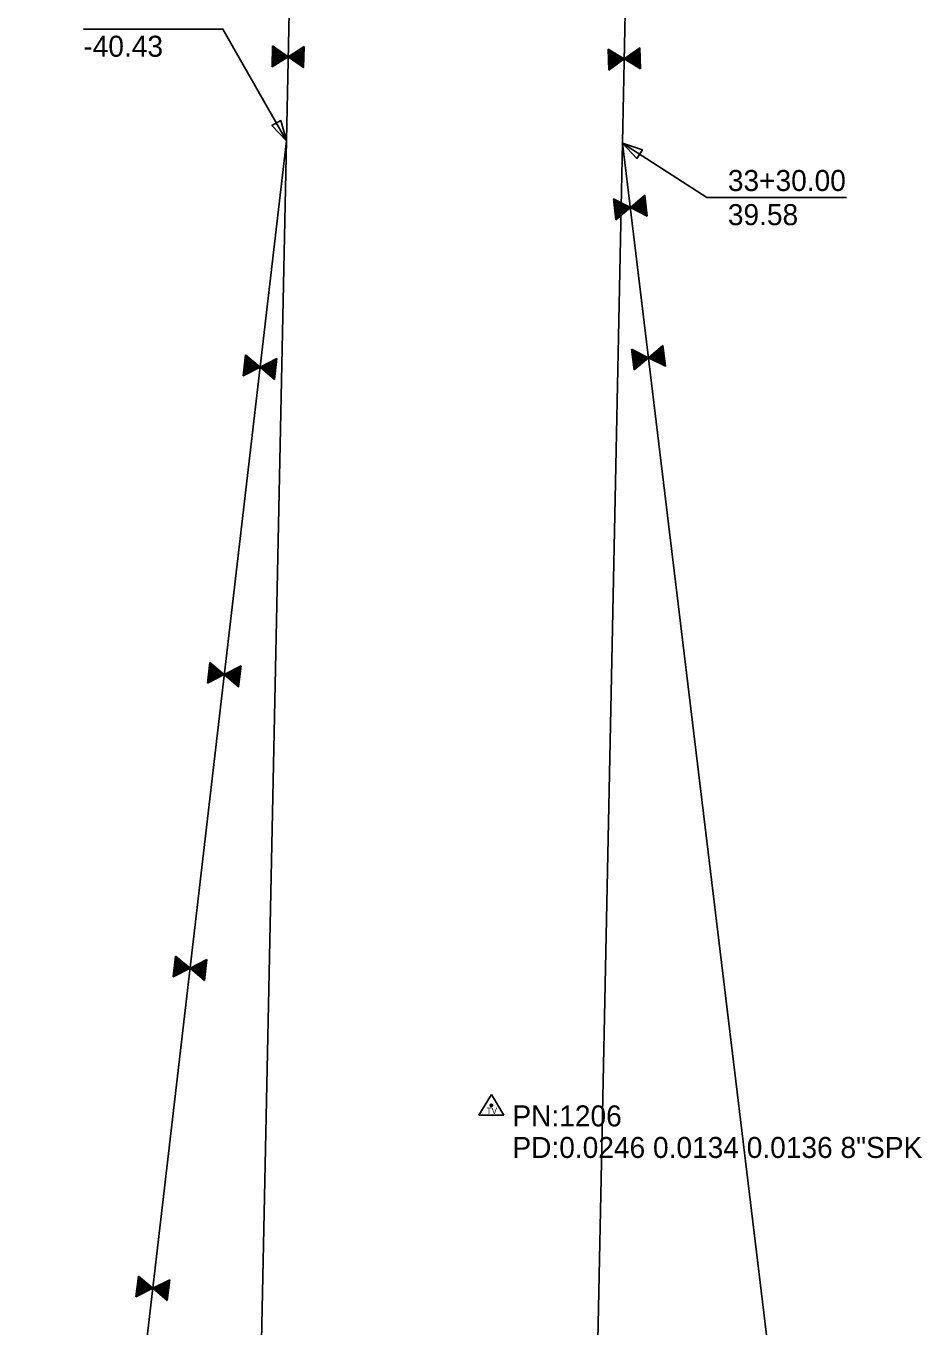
# Model space of a CAD drawing. Extents: x 1443798 to 1476449, y 2041559 to 2057889.
# Drawn here: x 1476148 to 1476361.3, y 2055786.4 to 2056095.8 of the extents above; entities that cross this region are included whole.
import ezdxf

# ---------------------------------------------------------------- set-up
doc = ezdxf.new("R2010")
doc.units = 0
for name, color, linetype in [('Plan Notes', 7, 'Continuous'), ('R_Proposed Fence', 7, 'Continuous'), ('R_ROW', 7, 'Continuous'), ('S_EXIST_ROW', 7, 'Continuous'), ('S_SECONDARY_CTL', 7, 'Continuous'), ('S_SECONDARY_CTL_ANNOT', 7, 'Continuous')]:
    doc.layers.add(name, color=color, linetype=linetype)

msp = doc.modelspace()

# ---------------------------------------------------------------- linework, layer by layer
at = {"layer": 'Plan Notes'}
for p, q in [((1476161.69, 2056095.07), (1476189.92, 2056095.07)), ((1476315.06, 2056055.02), (1476343.29, 2056055.02))]:
    msp.add_line(p, q, dxfattribs=at)
for points in [[(1476210, 2056068.52), (1476194.92, 2056095.07), (1476189.92, 2056095.07)], [(1476290.01, 2056067.99), (1476310.06, 2056055.02), (1476315.06, 2056055.02)]]:
    msp.add_lwpolyline(points, dxfattribs=at)
for points in [[(1476210, 2056068.52), (1476206.55, 2056072.14), (1476208.66, 2056073.34)], [(1476290.01, 2056067.99), (1476294.74, 2056066.37), (1476293.42, 2056064.34)]]:
    msp.add_lwpolyline(points, close=True, dxfattribs=at)
at = {"layer": 'R_Proposed Fence'}
for p, q in [((1476210.06, 2056088.37), (1476206.71, 2056090.7)), ((1476210.42, 2056088.52), (1476206.72, 2056091.1)), ((1476210.32, 2056088.48), (1476206.72, 2056091)), ((1476210.42, 2056088.52), (1476214.22, 2056090.94)), ((1476210.51, 2056088.48), (1476214.22, 2056090.84)), ((1476206.62, 2056086.1), (1476210.42, 2056088.52)), ((1476208.04, 2056087.03), (1476206.65, 2056087.99)), ((1476207.83, 2056086.87), (1476206.65, 2056087.69)), ((1476208.69, 2056087.49), (1476206.67, 2056088.9)), ((1476208.47, 2056087.34), (1476206.67, 2056088.6)), ((1476208.95, 2056087.61), (1476206.68, 2056089.2)), ((1476209.41, 2056087.9), (1476206.69, 2056089.8)), ((1476209.14, 2056087.79), (1476206.69, 2056089.5)), ((1476209.87, 2056088.19), (1476206.7, 2056090.4)), ((1476209.62, 2056088.06), (1476206.7, 2056090.1)), ((1476208.2, 2056087.22), (1476206.8, 2056088.2)), ((1476214.11, 2056085.94), (1476210.42, 2056088.52)), ((1476210.77, 2056088.35), (1476214.21, 2056090.54)), ((1476210.95, 2056088.17), (1476214.2, 2056090.24)), ((1476211.19, 2056088.03), (1476214.2, 2056089.94)), ((1476211.4, 2056087.86), (1476214.19, 2056089.64)), ((1476211.66, 2056087.73), (1476214.18, 2056089.34)), ((1476211.84, 2056087.55), (1476214.18, 2056089.04)), ((1476212.1, 2056087.42), (1476214.17, 2056088.74)), ((1476212.31, 2056087.26), (1476214.17, 2056088.44)), ((1476212.58, 2056087.13), (1476214.02, 2056088.05)), ((1476212.73, 2056086.93), (1476214.15, 2056087.84)), ((1476286.58, 2056090.35), (1476290.42, 2056087.99)), ((1476286.64, 2056090.29), (1476286.59, 2056090.25)), ((1476286.85, 2056090.14), (1476286.6, 2056089.95)), ((1476287.1, 2056090.01), (1476286.61, 2056089.65)), ((1476287.31, 2056089.85), (1476286.62, 2056089.35)), ((1476287.56, 2056089.73), (1476286.63, 2056089.05)), ((1476287.81, 2056089.59), (1476286.64, 2056088.75)), ((1476288.02, 2056089.44), (1476286.65, 2056088.45)), ((1476288.46, 2056089.14), (1476286.68, 2056087.85)), ((1476288.68, 2056088.99), (1476286.69, 2056087.55)), ((1476288.95, 2056088.87), (1476286.7, 2056087.25)), ((1476289.14, 2056088.7), (1476286.71, 2056086.95)), ((1476289.41, 2056088.59), (1476286.72, 2056086.65)), ((1476289.62, 2056088.44), (1476286.73, 2056086.35)), ((1476289.87, 2056088.31), (1476286.74, 2056086.05)), ((1476290.06, 2056088.14), (1476286.75, 2056085.75)), ((1476290.33, 2056088.02), (1476286.76, 2056085.45)), ((1476290.42, 2056087.99), (1476286.77, 2056085.35)), ((1476288.18, 2056089.25), (1476286.8, 2056088.25)), ((1476294.08, 2056090.63), (1476290.42, 2056087.99)), ((1476290.42, 2056087.99), (1476294.26, 2056085.63)), ((1476290.51, 2056088.03), (1476294.26, 2056085.73)), ((1476290.77, 2056088.16), (1476294.25, 2056086.03)), ((1476290.95, 2056088.35), (1476294.24, 2056086.33)), ((1476291.19, 2056088.5), (1476294.23, 2056086.63)), ((1476291.39, 2056088.66), (1476294.21, 2056086.93)), ((1476291.65, 2056088.8), (1476294.2, 2056087.23)), ((1476291.83, 2056088.98), (1476294.19, 2056087.53)), ((1476292.09, 2056089.11), (1476294.18, 2056087.83)), ((1476292.29, 2056089.28), (1476294.17, 2056088.13)), ((1476292.56, 2056089.41), (1476294.02, 2056088.52)), ((1476292.71, 2056089.62), (1476294.15, 2056088.73)), ((1476292.91, 2056089.78), (1476294.14, 2056089.03)), ((1476293.15, 2056089.93), (1476294.13, 2056089.33)), ((1476293.38, 2056090.08), (1476294.11, 2056089.63)), ((1476293.59, 2056090.25), (1476294.1, 2056089.93)), ((1476293.82, 2056090.4), (1476294.09, 2056090.23)), ((1476294.03, 2056090.57), (1476294.08, 2056090.53)), ((1476206.88, 2056086.31), (1476206.62, 2056086.49)), ((1476206.67, 2056086.16), (1476206.62, 2056086.19)), ((1476207.13, 2056086.45), (1476206.63, 2056086.79)), ((1476207.58, 2056086.74), (1476206.64, 2056087.39)), ((1476207.34, 2056086.6), (1476206.64, 2056087.09)), ((1476212.93, 2056086.77), (1476214.15, 2056087.54)), ((1476213.17, 2056086.62), (1476214.14, 2056087.24)), ((1476213.41, 2056086.48), (1476214.13, 2056086.94)), ((1476213.62, 2056086.31), (1476214.13, 2056086.64)), ((1476213.86, 2056086.17), (1476214.12, 2056086.34)), ((1476214.06, 2056086), (1476214.12, 2056086.04)), ((1476287.84, 2056054.69), (1476291.86, 2056052.66)), ((1476287.9, 2056054.64), (1476287.85, 2056054.6)), ((1476288.12, 2056054.5), (1476287.88, 2056054.3)), ((1476288.38, 2056054.4), (1476287.92, 2056054)), ((1476288.61, 2056054.26), (1476287.96, 2056053.7)), ((1476288.87, 2056054.15), (1476287.99, 2056053.4)), ((1476289.12, 2056054.04), (1476288.03, 2056053.1)), ((1476289.35, 2056053.91), (1476288.07, 2056052.81)), ((1476289.81, 2056053.64), (1476288.14, 2056052.21)), ((1476289.52, 2056053.73), (1476288.23, 2056052.62)), ((1476295.28, 2056055.59), (1476291.86, 2056052.66)), ((1476293.02, 2056053.56), (1476295.69, 2056052.21)), ((1476293.18, 2056053.76), (1476295.66, 2056052.51)), ((1476293.43, 2056053.92), (1476295.62, 2056052.81)), ((1476293.62, 2056054.1), (1476295.58, 2056053.11)), ((1476293.87, 2056054.25), (1476295.4, 2056053.48)), ((1476294, 2056054.47), (1476295.51, 2056053.71)), ((1476294.19, 2056054.65), (1476295.47, 2056054)), ((1476294.41, 2056054.82), (1476295.44, 2056054.3)), ((1476294.64, 2056054.99), (1476295.4, 2056054.6)), ((1476294.82, 2056055.17), (1476295.37, 2056054.9)), ((1476295.05, 2056055.34), (1476295.33, 2056055.2)), ((1476295.24, 2056055.53), (1476295.29, 2056055.5)), ((1476290.04, 2056053.51), (1476288.17, 2056051.91)), ((1476290.32, 2056053.42), (1476288.21, 2056051.61)), ((1476290.52, 2056053.26), (1476288.25, 2056051.31)), ((1476290.8, 2056053.17), (1476288.28, 2056051.02)), ((1476291.02, 2056053.04), (1476288.32, 2056050.72)), ((1476291.28, 2056052.93), (1476288.35, 2056050.42)), ((1476291.49, 2056052.77), (1476288.39, 2056050.12)), ((1476291.76, 2056052.68), (1476288.43, 2056049.82)), ((1476291.86, 2056052.66), (1476288.44, 2056049.73)), ((1476291.86, 2056052.66), (1476295.88, 2056050.63)), ((1476291.95, 2056052.71), (1476295.87, 2056050.72)), ((1476292.2, 2056052.86), (1476295.84, 2056051.02)), ((1476292.36, 2056053.06), (1476295.8, 2056051.32)), ((1476292.58, 2056053.23), (1476295.76, 2056051.62)), ((1476292.77, 2056053.41), (1476295.73, 2056051.92)), ((1476296.18, 2056016.95), (1476299.6, 2056019.88)), ((1476296.27, 2056016.92), (1476299.61, 2056019.78)), ((1476202.89, 2056014.29), (1476200.18, 2056016.6)), ((1476203.15, 2056014.4), (1476200.21, 2056016.9)), ((1476203.36, 2056014.56), (1476200.25, 2056017.19)), ((1476203.63, 2056014.65), (1476200.28, 2056017.49)), ((1476203.73, 2056014.67), (1476200.29, 2056017.59)), ((1476203.73, 2056014.67), (1476207.74, 2056016.72)), ((1476203.82, 2056014.63), (1476207.73, 2056016.63)), ((1476296.18, 2056016.95), (1476292.15, 2056018.98)), ((1476296.09, 2056016.9), (1476292.17, 2056018.88)), ((1476295.84, 2056016.75), (1476292.2, 2056018.58)), ((1476295.68, 2056016.55), (1476292.24, 2056018.28)), ((1476295.45, 2056016.38), (1476292.27, 2056017.99)), ((1476295.27, 2056016.2), (1476292.31, 2056017.69)), ((1476295.02, 2056016.04), (1476292.35, 2056017.39)), ((1476294.86, 2056015.84), (1476292.38, 2056017.09)), ((1476294.61, 2056015.69), (1476292.42, 2056016.79)), ((1476294.42, 2056015.5), (1476292.45, 2056016.5)), ((1476292.75, 2056014.02), (1476296.18, 2056016.95)), ((1476300.2, 2056014.92), (1476296.18, 2056016.95)), ((1476296.55, 2056016.83), (1476299.65, 2056019.48)), ((1476296.76, 2056016.68), (1476299.68, 2056019.18)), ((1476297.01, 2056016.57), (1476299.72, 2056018.89)), ((1476297.24, 2056016.43), (1476299.76, 2056018.59)), ((1476297.52, 2056016.34), (1476299.79, 2056018.29)), ((1476297.72, 2056016.19), (1476299.83, 2056017.99)), ((1476298, 2056016.1), (1476299.86, 2056017.69)), ((1476298.23, 2056015.96), (1476299.9, 2056017.4)), ((1476298.51, 2056015.88), (1476299.81, 2056016.99)), ((1476298.69, 2056015.7), (1476299.97, 2056016.8)), ((1476298.92, 2056015.57), (1476300.01, 2056016.5)), ((1476199.72, 2056012.63), (1476203.73, 2056014.67)), ((1476200.48, 2056013.06), (1476199.83, 2056013.61)), ((1476200.74, 2056013.17), (1476199.87, 2056013.91)), ((1476201, 2056013.28), (1476199.9, 2056014.21)), ((1476201.22, 2056013.42), (1476199.94, 2056014.51)), ((1476201.68, 2056013.68), (1476200, 2056015.11)), ((1476201.91, 2056013.82), (1476200.04, 2056015.4)), ((1476202.19, 2056013.91), (1476200.07, 2056015.7)), ((1476201.4, 2056013.59), (1476200.1, 2056014.7)), ((1476202.39, 2056014.06), (1476200.11, 2056016)), ((1476202.67, 2056014.16), (1476200.14, 2056016.3)), ((1476207.17, 2056011.76), (1476203.73, 2056014.67)), ((1476204.07, 2056014.47), (1476207.7, 2056016.33)), ((1476204.23, 2056014.28), (1476207.66, 2056016.03)), ((1476204.45, 2056014.11), (1476207.63, 2056015.73)), ((1476204.64, 2056013.93), (1476207.59, 2056015.43)), ((1476204.89, 2056013.77), (1476207.56, 2056015.13)), ((1476205.05, 2056013.57), (1476207.52, 2056014.84)), ((1476205.3, 2056013.42), (1476207.49, 2056014.54)), ((1476205.49, 2056013.24), (1476207.45, 2056014.24)), ((1476205.75, 2056013.09), (1476207.27, 2056013.86)), ((1476205.88, 2056012.87), (1476207.38, 2056013.64)), ((1476206.07, 2056012.69), (1476207.35, 2056013.34)), ((1476294.03, 2056015.14), (1476292.53, 2056015.9)), ((1476293.85, 2056014.95), (1476292.56, 2056015.6)), ((1476293.62, 2056014.78), (1476292.6, 2056015.3)), ((1476293.4, 2056014.62), (1476292.63, 2056015)), ((1476294.16, 2056015.35), (1476292.64, 2056016.12)), ((1476293.21, 2056014.43), (1476292.67, 2056014.71)), ((1476292.99, 2056014.27), (1476292.71, 2056014.41)), ((1476292.8, 2056014.08), (1476292.74, 2056014.11)), ((1476299.17, 2056015.46), (1476300.04, 2056016.2)), ((1476299.43, 2056015.35), (1476300.08, 2056015.9)), ((1476299.66, 2056015.21), (1476300.12, 2056015.61)), ((1476299.91, 2056015.1), (1476300.15, 2056015.31)), ((1476300.14, 2056014.97), (1476300.19, 2056015.01)), ((1476199.78, 2056012.68), (1476199.73, 2056012.72)), ((1476200, 2056012.81), (1476199.76, 2056013.02)), ((1476200.26, 2056012.92), (1476199.8, 2056013.31)), ((1476206.29, 2056012.52), (1476207.32, 2056013.04)), ((1476206.52, 2056012.36), (1476207.28, 2056012.75)), ((1476206.71, 2056012.17), (1476207.25, 2056012.45)), ((1476206.93, 2056012.01), (1476207.21, 2056012.15)), ((1476207.12, 2056011.82), (1476207.18, 2056011.85)), ((1476193.4, 2055940.72), (1476191.53, 2055942.31)), ((1476193.67, 2055940.81), (1476191.56, 2055942.61)), ((1476193.88, 2055940.97), (1476191.6, 2055942.91)), ((1476194.16, 2055941.06), (1476191.63, 2055943.2)), ((1476194.38, 2055941.19), (1476191.67, 2055943.5)), ((1476194.64, 2055941.3), (1476191.7, 2055943.8)), ((1476194.84, 2055941.46), (1476191.74, 2055944.1)), ((1476195.12, 2055941.55), (1476191.77, 2055944.4)), ((1476195.22, 2055941.58), (1476191.78, 2055944.5)), ((1476195.22, 2055941.58), (1476199.23, 2055943.63)), ((1476195.3, 2055941.53), (1476199.22, 2055943.53)), ((1476195.55, 2055941.38), (1476199.19, 2055943.23)), ((1476195.72, 2055941.18), (1476199.15, 2055942.93)), ((1476195.94, 2055941.01), (1476199.12, 2055942.63)), ((1476196.13, 2055940.83), (1476199.08, 2055942.34)), ((1476191.2, 2055939.53), (1476195.22, 2055941.58)), ((1476191.26, 2055939.58), (1476191.21, 2055939.62)), ((1476191.49, 2055939.72), (1476191.25, 2055939.92)), ((1476191.75, 2055939.83), (1476191.28, 2055940.22)), ((1476191.97, 2055939.96), (1476191.32, 2055940.52)), ((1476192.23, 2055940.07), (1476191.35, 2055940.82)), ((1476192.48, 2055940.18), (1476191.39, 2055941.11)), ((1476192.71, 2055940.32), (1476191.42, 2055941.41)), ((1476193.17, 2055940.58), (1476191.49, 2055942.01)), ((1476192.89, 2055940.5), (1476191.58, 2055941.6)), ((1476198.65, 2055938.66), (1476195.22, 2055941.58)), ((1476196.38, 2055940.68), (1476199.05, 2055942.04)), ((1476196.54, 2055940.48), (1476199.01, 2055941.74)), ((1476196.79, 2055940.33), (1476198.98, 2055941.44)), ((1476196.98, 2055940.14), (1476198.94, 2055941.14)), ((1476197.24, 2055939.99), (1476198.76, 2055940.77)), ((1476197.37, 2055939.78), (1476198.87, 2055940.55)), ((1476197.56, 2055939.59), (1476198.84, 2055940.25)), ((1476197.78, 2055939.43), (1476198.8, 2055939.95)), ((1476198.01, 2055939.26), (1476198.77, 2055939.65)), ((1476198.19, 2055939.07), (1476198.73, 2055939.35)), ((1476198.42, 2055938.91), (1476198.7, 2055939.05)), ((1476198.61, 2055938.72), (1476198.66, 2055938.75)), ((1476186.71, 2055871.63), (1476183.6, 2055874.27)), ((1476186.99, 2055871.72), (1476183.64, 2055874.56)), ((1476187.09, 2055871.75), (1476183.65, 2055874.66)), ((1476183.07, 2055869.7), (1476187.09, 2055871.75)), ((1476184.35, 2055870.35), (1476183.26, 2055871.28)), ((1476184.58, 2055870.49), (1476183.29, 2055871.58)), ((1476185.04, 2055870.75), (1476183.36, 2055872.18)), ((1476185.27, 2055870.89), (1476183.4, 2055872.48)), ((1476185.54, 2055870.98), (1476183.43, 2055872.77)), ((1476184.75, 2055870.67), (1476183.45, 2055871.77)), ((1476185.75, 2055871.14), (1476183.46, 2055873.07)), ((1476186.03, 2055871.23), (1476183.5, 2055873.37)), ((1476186.25, 2055871.36), (1476183.53, 2055873.67)), ((1476186.51, 2055871.47), (1476183.57, 2055873.97)), ((1476187.09, 2055871.75), (1476191.1, 2055873.8)), ((1476190.52, 2055868.83), (1476187.09, 2055871.75)), ((1476187.17, 2055871.7), (1476191.09, 2055873.7)), ((1476187.42, 2055871.54), (1476191.05, 2055873.4)), ((1476187.59, 2055871.35), (1476191.02, 2055873.1)), ((1476187.81, 2055871.18), (1476190.98, 2055872.8)), ((1476188, 2055871), (1476190.95, 2055872.5)), ((1476188.25, 2055870.84), (1476190.91, 2055872.21)), ((1476188.41, 2055870.65), (1476190.88, 2055871.91)), ((1476188.66, 2055870.49), (1476190.84, 2055871.61)), ((1476188.85, 2055870.31), (1476190.81, 2055871.31)), ((1476183.13, 2055869.75), (1476183.08, 2055869.79)), ((1476183.36, 2055869.88), (1476183.12, 2055870.09)), ((1476183.61, 2055869.99), (1476183.15, 2055870.39)), ((1476183.84, 2055870.13), (1476183.19, 2055870.69)), ((1476184.1, 2055870.24), (1476183.22, 2055870.98)), ((1476189.11, 2055870.16), (1476190.63, 2055870.94)), ((1476189.24, 2055869.95), (1476190.74, 2055870.71)), ((1476189.43, 2055869.76), (1476190.71, 2055870.42)), ((1476189.65, 2055869.59), (1476190.67, 2055870.12)), ((1476189.87, 2055869.43), (1476190.64, 2055869.82)), ((1476190.06, 2055869.24), (1476190.6, 2055869.52)), ((1476190.29, 2055869.08), (1476190.57, 2055869.22)), ((1476190.47, 2055868.89), (1476190.53, 2055868.92)), ((1476176.88, 2055795.03), (1476174.6, 2055796.96)), ((1476177.16, 2055795.12), (1476174.64, 2055797.26)), ((1476177.39, 2055795.25), (1476174.67, 2055797.56)), ((1476177.64, 2055795.36), (1476174.71, 2055797.86)), ((1476177.85, 2055795.52), (1476174.74, 2055798.16)), ((1476178.13, 2055795.61), (1476174.78, 2055798.46)), ((1476178.22, 2055795.64), (1476174.79, 2055798.55)), ((1476178.22, 2055795.64), (1476182.24, 2055797.69)), ((1476178.31, 2055795.59), (1476182.22, 2055797.59)), ((1476178.56, 2055795.44), (1476182.19, 2055797.29)), ((1476178.72, 2055795.24), (1476182.16, 2055796.99)), ((1476174.21, 2055793.59), (1476178.22, 2055795.64)), ((1476174.27, 2055793.64), (1476174.22, 2055793.68)), ((1476174.49, 2055793.78), (1476174.25, 2055793.98)), ((1476174.75, 2055793.88), (1476174.29, 2055794.28)), ((1476174.98, 2055794.02), (1476174.32, 2055794.58)), ((1476175.23, 2055794.13), (1476174.36, 2055794.87)), ((1476175.49, 2055794.24), (1476174.39, 2055795.17)), ((1476175.72, 2055794.38), (1476174.43, 2055795.47)), ((1476176.18, 2055794.64), (1476174.5, 2055796.07)), ((1476176.4, 2055794.78), (1476174.53, 2055796.37)), ((1476176.68, 2055794.87), (1476174.57, 2055796.67)), ((1476175.89, 2055794.56), (1476174.59, 2055795.66)), ((1476181.66, 2055792.72), (1476178.22, 2055795.64)), ((1476178.95, 2055795.07), (1476182.12, 2055796.69)), ((1476179.13, 2055794.89), (1476182.09, 2055796.4)), ((1476179.38, 2055794.74), (1476182.05, 2055796.1)), ((1476179.55, 2055794.54), (1476182.02, 2055795.8)), ((1476179.8, 2055794.38), (1476181.98, 2055795.5)), ((1476179.98, 2055794.2), (1476181.95, 2055795.2)), ((1476180.24, 2055794.05), (1476181.76, 2055794.83)), ((1476180.37, 2055793.84), (1476181.88, 2055794.6)), ((1476180.56, 2055793.65), (1476181.84, 2055794.31)), ((1476180.78, 2055793.49), (1476181.81, 2055794.01)), ((1476181.01, 2055793.32), (1476181.77, 2055793.71)), ((1476181.2, 2055793.13), (1476181.74, 2055793.41)), ((1476181.42, 2055792.97), (1476181.7, 2055793.11)), ((1476181.61, 2055792.78), (1476181.67, 2055792.81))]:
    msp.add_line(p, q, dxfattribs=at)
for points in [[(1476206.62, 2056086.1), (1476206.72, 2056091.1)], [(1476214.11, 2056085.94), (1476214.22, 2056090.94)], [(1476286.58, 2056090.35), (1476286.77, 2056085.35)], [(1476294.08, 2056090.63), (1476294.26, 2056085.63)], [(1476287.84, 2056054.69), (1476288.44, 2056049.73)], [(1476295.28, 2056055.59), (1476295.88, 2056050.63)], [(1476300.2, 2056014.92), (1476299.6, 2056019.88)], [(1476199.72, 2056012.63), (1476200.29, 2056017.59)], [(1476207.17, 2056011.76), (1476207.74, 2056016.72)], [(1476292.75, 2056014.02), (1476292.15, 2056018.98)], [(1476191.2, 2055939.53), (1476191.78, 2055944.5)], [(1476198.65, 2055938.66), (1476199.23, 2055943.63)], [(1476183.07, 2055869.7), (1476183.65, 2055874.66)], [(1476190.52, 2055868.83), (1476191.1, 2055873.8)], [(1476174.21, 2055793.59), (1476174.79, 2055798.55)], [(1476181.66, 2055792.72), (1476182.24, 2055797.69)]]:
    msp.add_lwpolyline(points, dxfattribs=at)
at = {"layer": 'R_ROW'}
for points in [[(1476186.62, 2054859.81), (1476148.84, 2054931.09), (1476150.62, 2055015.03), (1476181.31, 2055049.43), (1476148.04, 2055390.15), (1476173.45, 2055511.72), (1476163.58, 2055669.9), (1476210, 2056068.52)], [(1476266.59, 2054857.19), (1476319.08, 2054935.51), (1476286.09, 2055037.35), (1476312.02, 2055336.9), (1476343.4, 2055406.29), (1476319.91, 2055508.84), (1476306.57, 2055567.05), (1476338.55, 2055666.44), (1476290.01, 2056067.99)]]:
    msp.add_lwpolyline(points, dxfattribs=at)
at = {"layer": 'S_EXIST_ROW'}
for p, q in [((1476196.03, 2055396.48), (1476234.51, 2057247.25)), ((1476278.12, 2055496.04), (1476305.28, 2056802.66))]:
    msp.add_line(p, q, dxfattribs=at)
at = {"layer": 'S_SECONDARY_CTL'}
for p, q in [((1476258.79, 2055841.75), (1476255.78, 2055836.79)), ((1476258.79, 2055841.75), (1476261.74, 2055836.79)), ((1476255.78, 2055836.79), (1476261.74, 2055836.79))]:
    msp.add_line(p, q, dxfattribs=at)
for radius in [0.311, 0.183, 0.103]:
    msp.add_circle((1476258.79, 2055839.14), radius, dxfattribs=at)

# ---------------------------------------------------------------- texts
at = {"layer": 'Plan Notes'}
for s, p in [('-40.43', (1476161.69, 2056088.51)), ('33+30.00', (1476315.06, 2056056.58)), ('39.58', (1476315.06, 2056048.46))]:
    msp.add_text(s, height=5, dxfattribs=at).set_placement(p)
at = {"layer": 'S_SECONDARY_CTL'}
msp.add_text('TV', height=1.5, dxfattribs=at).set_placement((1476257.59, 2055837.13))
at = {"layer": 'S_SECONDARY_CTL_ANNOT'}
for s, p in [('PN:1206', (1476263.79, 2055834.14)), ('PD:0.0246 0.0134 0.0136 8"SPK', (1476263.79, 2055826.64))]:
    msp.add_text(s, height=5, dxfattribs=at).set_placement(p)

doc.saveas('drawing.dxf')
